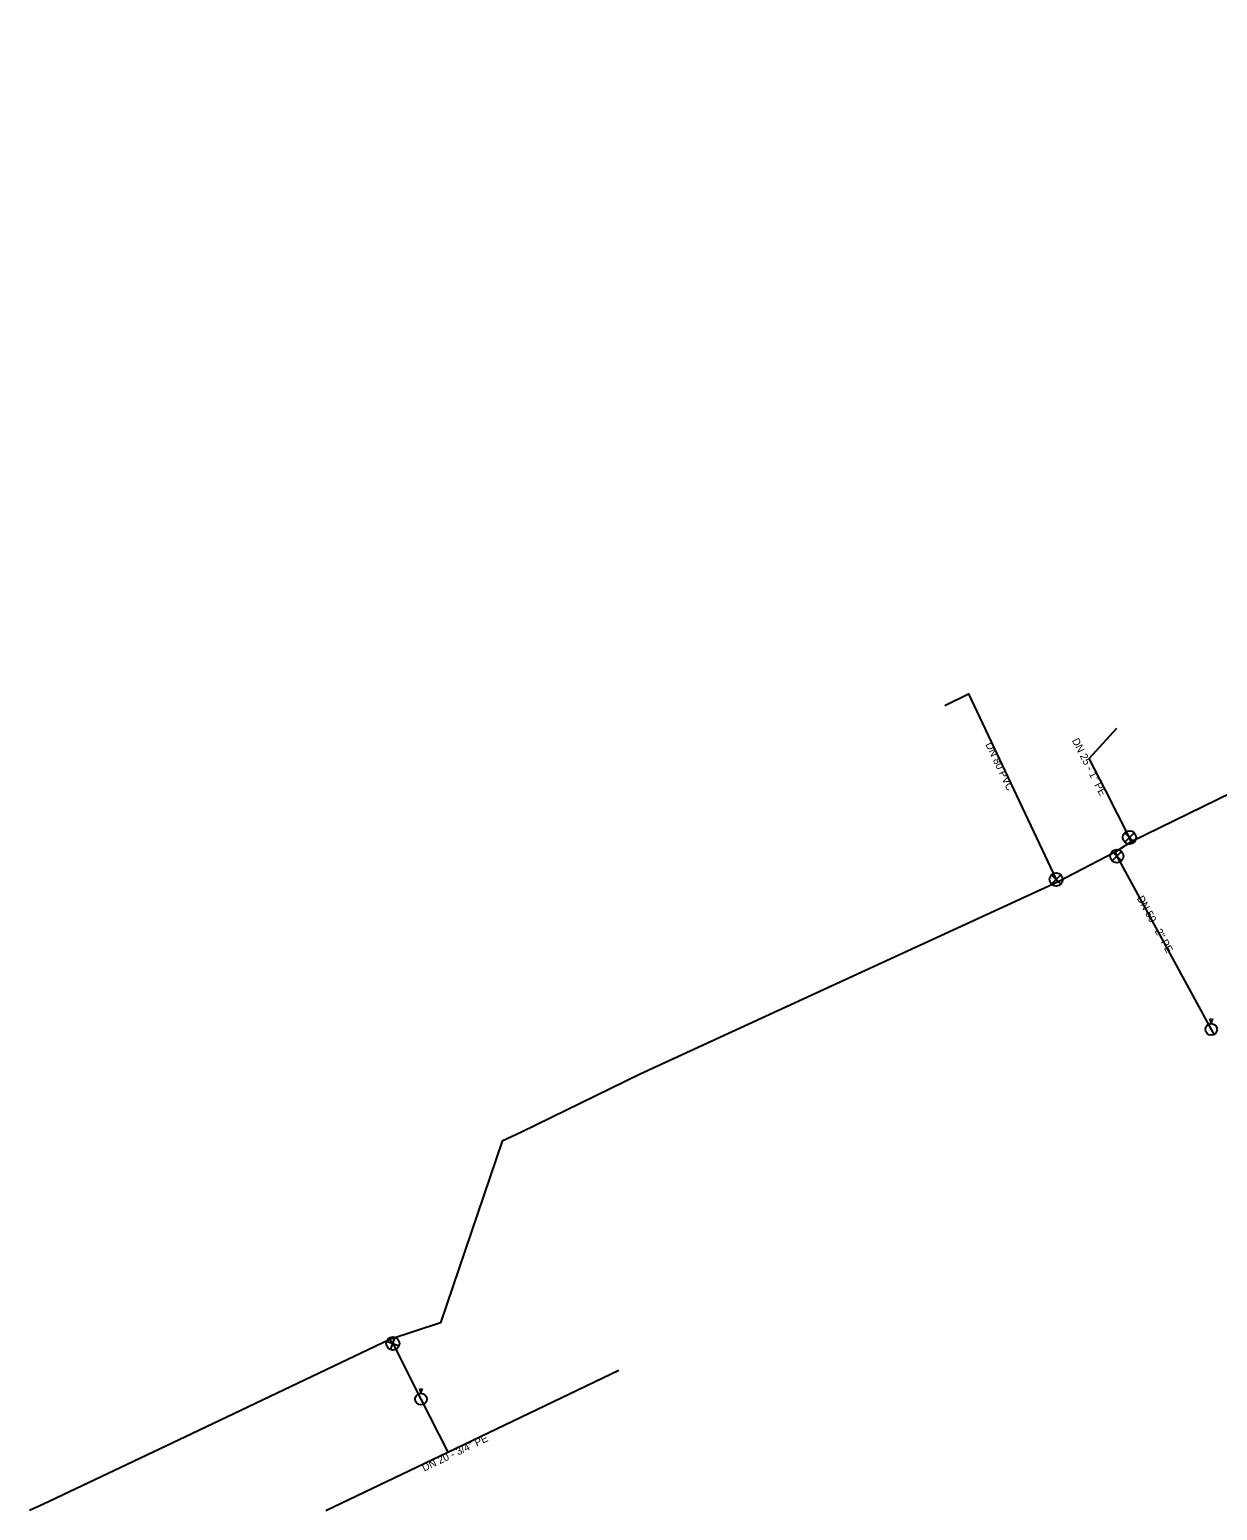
# Model space of a CAD drawing. Extents: x -492390 to -492189, y -1126311 to -1126155.
# Drawn here: x -492357 to -492285.4, y -1126310.9 to -1126221.6 of the extents above; entities that cross this region are included whole.
import ezdxf

# ---------------------------------------------------------------- set-up
doc = ezdxf.new("R2010")
doc.units = 0
for name, color, linetype in [('_pripojka_prevzato_z_dokumentace_', 7, 'Continuous'), ('_pripojka_priblizne_', 7, 'Continuous'), ('_voda_smvak_prevzato_z_dokumentace_', 7, 'Continuous'), ('Default', 7, 'Continuous'), ('MoLevel 30', 7, 'Continuous'), ('MoLevel 32', 7, 'Continuous'), ('MoLevel 53', 7, 'Continuous'), ('MoLevel 55', 7, 'Continuous')]:
    doc.layers.add(name, color=color, linetype=linetype)

# ---------------------------------------------------------------- blocks, each defined once
blk = doc.blocks.new('_uzaver_pripojka_')
at = {"layer": 'Default'}
for p, q in [((-0.000035, -0.000035), (0.000035, 0.000035)), ((0.000035, -0.000035), (-0.000035, 0.000035))]:
    blk.add_line(p, q, dxfattribs=at)
for radius in [0.00005, 0.0000025]:
    blk.add_circle((0, 0), radius, dxfattribs=at)
blk = doc.blocks.new('_sachta_voda_')
at = {"layer": 'Default'}
blk.add_lwpolyline([(-0.00001, 0.000065), (0, 0.000035), (0.00001, 0.000065)], dxfattribs=at)
blk.add_circle((0, 0), 0.000035, dxfattribs=at)

msp = doc.modelspace()

# ---------------------------------------------------------------- linework, layer by layer
at = {"layer": '_pripojka_prevzato_z_dokumentace_'}
for p, q in [((-492285.744, -1126281.92), (-492285.568, -1126282.243)), ((-492339.158, -1126310.938), (-492331.805, -1126307.418))]:
    msp.add_line(p, q, dxfattribs=at)
for points in [[(-492301.826, -1126262.393), (-492300.389, -1126261.69), (-492295.1, -1126272.88), (-492295.01, -1126273.05)], [(-492291.54, -1126271.24), (-492291.44, -1126271.47), (-492285.744, -1126281.92)], [(-492335.31, -1126300.63), (-492335.12, -1126300.87), (-492333.421, -1126304.226)], [(-492333.421, -1126304.226), (-492331.805, -1126307.418), (-492321.483, -1126302.478)]]:
    msp.add_lwpolyline(points, dxfattribs=at)
at = {"layer": '_pripojka_priblizne_'}
for points in [[(-492292.128, -1126267.492), (-492293.1, -1126265.58), (-492291.442, -1126263.752)], [(-492290.57, -1126270.6), (-492290.68, -1126270.34), (-492292.128, -1126267.492)]]:
    msp.add_lwpolyline(points, dxfattribs=at)
at = {"layer": '_voda_smvak_prevzato_z_dokumentace_'}
for points in [[(-492189.265, -1126221.613), (-492191, -1126222.53), (-492201.62, -1126227.71), (-492207.05, -1126230.3), (-492207.64, -1126230.59), (-492219.88, -1126236.55), (-492224.69, -1126238.73), (-492239.58, -1126245.83), (-492247.43, -1126249.64), (-492248.33, -1126250.02), (-492250.84, -1126251.26), (-492265.59, -1126258.52), (-492278.43, -1126264.67), (-492290.57, -1126270.6), (-492291.54, -1126271.24), (-492295.01, -1126273.05), (-492320.201, -1126284.62), (-492327.358, -1126288.114)], [(-492327.358, -1126288.114), (-492328.533, -1126288.67), (-492332.24, -1126299.62), (-492335.31, -1126300.63), (-492347.25, -1126306.312), (-492356.2, -1126310.57), (-492357.034, -1126310.938)]]:
    msp.add_lwpolyline(points, dxfattribs=at)

# ---------------------------------------------------------------- block references
at = {"layer": 'MoLevel 30', "xscale": 10000, "yscale": 10000}
for p in [(-492285.744, -1126281.92), (-492333.421, -1126304.226)]:
    msp.add_blockref('_sachta_voda_', p, dxfattribs=at)
at = {"layer": 'MoLevel 53', "xscale": 7999.999999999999, "yscale": 7999.999999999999}
for p in [(-492290.68, -1126270.34), (-492291.44, -1126271.47), (-492295.1, -1126272.88)]:
    msp.add_blockref('_uzaver_pripojka_', p, dxfattribs=at)
at = {"layer": 'MoLevel 53', "xscale": 8000.000000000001, "yscale": 8000, "rotation": -64.42056944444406}
msp.add_blockref('_uzaver_pripojka_', (-492335.12, -1126300.87), dxfattribs=at)

# ---------------------------------------------------------------- texts
at = {"layer": 'MoLevel 32'}
msp.add_text("DN 25 - 1'' PE", height=0.455, rotation=296.95232, dxfattribs=at).set_placement((-492294.164, -1126264.491))
at = {"layer": 'MoLevel 55'}
for s, rotation, p in [('DN 80 PVC', 295.29796, (-492299.379, -1126264.729)), ("DN 50 - 2'' PE", 298.59332, (-492290.246, -1126274.01)), ("DN 20 - 3/4'' PE", 25.57528, (-492333.228, -1126308.604))]:
    msp.add_text(s, height=0.455, rotation=rotation, dxfattribs=at).set_placement(p)

doc.saveas('drawing.dxf')
